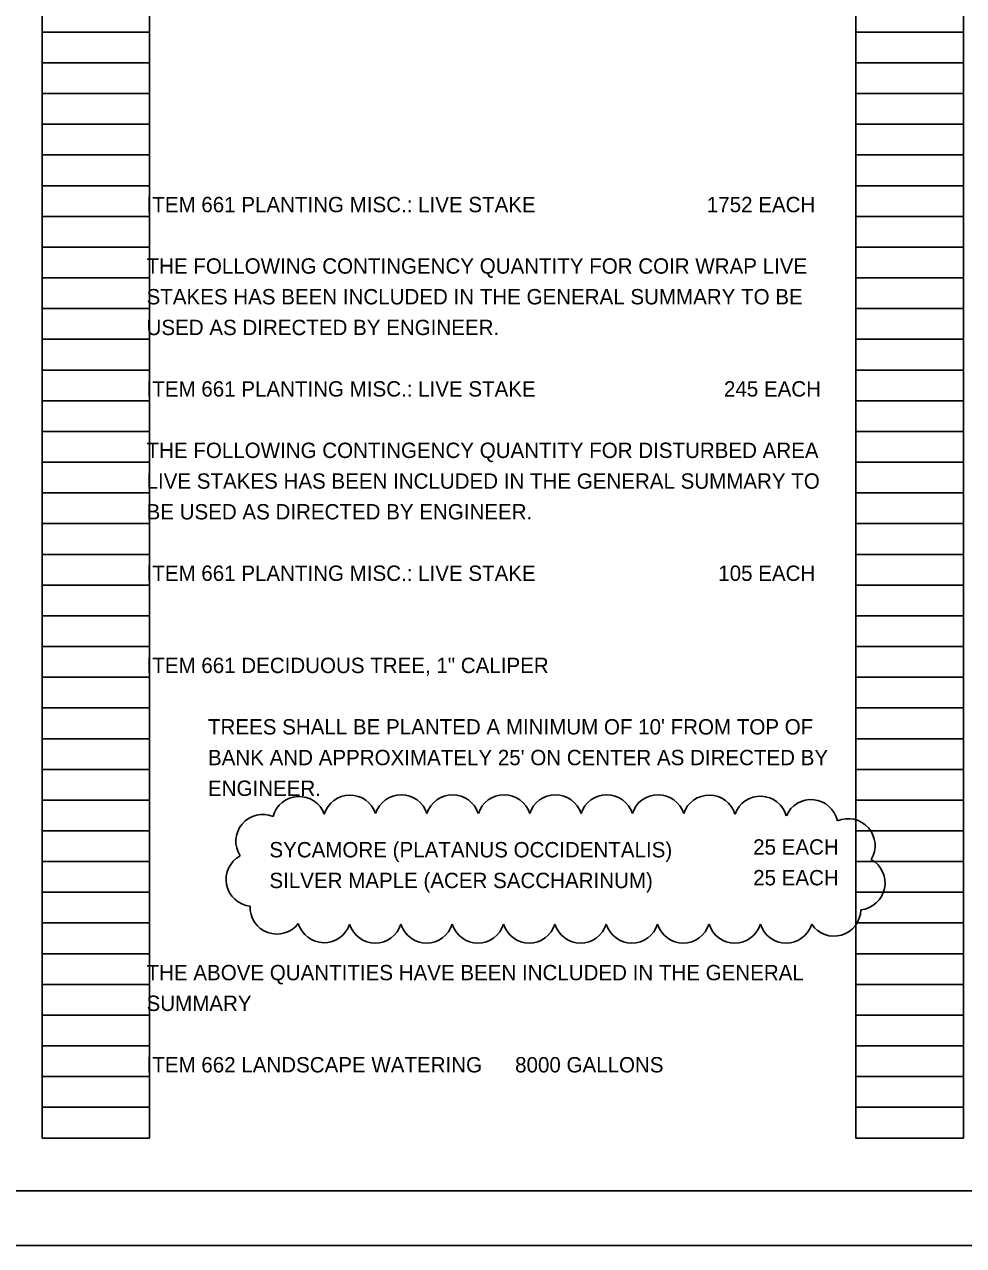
# Model space of a CAD drawing. Extents: x 0 to 34, y 0 to 22.
# Drawn here: x 16.1 to 24.66, y 0 to 11.13 of the extents above; entities that cross this region are included whole.
import ezdxf

# ---------------------------------------------------------------- set-up
doc = ezdxf.new("R2010")
doc.units = 0
for name, color, linetype in [('CS-ALGN-CNTR', 7, 'Continuous'), ('CS-ALGN-TEXT', 7, 'Continuous'), ('CS-ANNO-MATC', 7, 'Continuous'), ('CS-ANNO-MATC-MASK', 7, 'Continuous'), ('CS-ANNO-TABL', 7, 'Continuous')]:
    doc.layers.add(name, color=color, linetype=linetype)

msp = doc.modelspace()

# ---------------------------------------------------------------- linework, layer by layer
at = {"layer": 'CS-ALGN-CNTR'}
msp.add_lwpolyline([(0, 0), (34, 0), (34, 22), (0, 22)], close=True, dxfattribs=at)
at = {"layer": 'CS-ALGN-TEXT'}
msp.add_lwpolyline([(1.5, 21.5), (33.5, 21.5), (33.5, 0.5), (1.5, 0.5)], close=True, dxfattribs=at)
at = {"layer": 'CS-ANNO-MATC-MASK'}
for p, q in [((16.26, 0.98), (16.26, 21.14)), ((17.24, 0.98), (17.24, 21.14)), ((23.68, 0.98), (23.68, 21.14)), ((24.66, 0.98), (24.66, 21.14)), ((16.26, 11.06), (17.24, 11.06)), ((23.68, 11.06), (24.66, 11.06)), ((16.26, 10.78), (17.24, 10.78)), ((23.68, 10.78), (24.66, 10.78)), ((16.26, 10.5), (17.24, 10.5)), ((23.68, 10.5), (24.66, 10.5)), ((16.26, 10.22), (17.24, 10.22)), ((23.68, 10.22), (24.66, 10.22)), ((16.26, 9.94), (17.24, 9.94)), ((23.68, 9.94), (24.66, 9.94)), ((16.26, 9.66), (17.24, 9.66)), ((23.68, 9.66), (24.66, 9.66)), ((16.26, 9.38), (17.24, 9.38)), ((23.68, 9.38), (24.66, 9.38)), ((16.26, 9.1), (17.24, 9.1)), ((23.68, 9.1), (24.66, 9.1)), ((16.26, 8.82), (17.24, 8.82)), ((23.68, 8.82), (24.66, 8.82)), ((16.26, 8.54), (17.24, 8.54)), ((23.68, 8.54), (24.66, 8.54)), ((16.26, 8.26), (17.24, 8.26)), ((23.68, 8.26), (24.66, 8.26)), ((16.26, 7.98), (17.24, 7.98)), ((23.68, 7.98), (24.66, 7.98)), ((16.26, 7.7), (17.24, 7.7)), ((23.68, 7.7), (24.66, 7.7)), ((16.26, 7.42), (17.24, 7.42)), ((23.68, 7.42), (24.66, 7.42)), ((16.26, 7.14), (17.24, 7.14)), ((23.68, 7.14), (24.66, 7.14)), ((16.26, 6.86), (17.24, 6.86)), ((23.68, 6.86), (24.66, 6.86)), ((16.26, 6.58), (17.24, 6.58)), ((23.68, 6.58), (24.66, 6.58)), ((16.26, 6.3), (17.24, 6.3)), ((23.68, 6.3), (24.66, 6.3)), ((16.26, 6.02), (17.24, 6.02)), ((23.68, 6.02), (24.66, 6.02)), ((16.26, 5.74), (17.24, 5.74)), ((23.68, 5.74), (24.66, 5.74)), ((16.26, 5.46), (17.24, 5.46)), ((23.68, 5.46), (24.66, 5.46)), ((16.26, 5.18), (17.24, 5.18)), ((23.68, 5.18), (24.66, 5.18)), ((16.26, 4.9), (17.24, 4.9)), ((23.68, 4.9), (24.66, 4.9)), ((16.26, 4.62), (17.24, 4.62)), ((23.68, 4.62), (24.66, 4.62)), ((16.26, 4.34), (17.24, 4.34)), ((23.68, 4.34), (24.66, 4.34)), ((16.26, 4.06), (17.24, 4.06)), ((23.68, 4.06), (24.66, 4.06)), ((16.26, 3.78), (17.24, 3.78)), ((23.68, 3.78), (24.66, 3.78)), ((16.26, 3.5), (17.24, 3.5)), ((23.68, 3.5), (24.66, 3.5)), ((16.26, 3.22), (17.24, 3.22)), ((23.68, 3.22), (24.66, 3.22)), ((16.26, 2.94), (17.24, 2.94)), ((23.68, 2.94), (24.66, 2.94)), ((16.26, 2.66), (17.24, 2.66)), ((23.68, 2.66), (24.66, 2.66)), ((16.26, 2.38), (17.24, 2.38)), ((23.68, 2.38), (24.66, 2.38)), ((16.26, 2.1), (17.24, 2.1)), ((23.68, 2.1), (24.66, 2.1)), ((16.26, 1.82), (17.24, 1.82)), ((23.68, 1.82), (24.66, 1.82)), ((16.26, 1.54), (17.24, 1.54)), ((23.68, 1.54), (24.66, 1.54)), ((16.26, 1.26), (17.24, 1.26)), ((23.68, 1.26), (24.66, 1.26)), ((16.26, 0.98), (17.24, 0.98)), ((23.68, 0.98), (24.66, 0.98))]:
    msp.add_line(p, q, dxfattribs=at)
at = {"layer": 'CS-ANNO-TABL'}
for centre, start, end in [((18.603, 3.848), 20.1591, 165.1591), ((19.068, 3.861), 18.1234, 163.1234), ((19.535, 3.864), 17.5117, 162.5117), ((20.003, 3.864), 17.5, 162.5), ((20.472, 3.864), 17.5, 162.5), ((20.94, 3.864), 17.5, 162.5), ((21.408, 3.864), 17.5, 162.5), ((21.876, 3.864), 17.4512, 162.4512), ((22.343, 3.861), 16.8459, 161.8459), ((22.809, 3.851), 15.5867, 160.5867), ((23.271, 3.82), 11.8643, 156.8643), ((18.272, 3.684), 67.4687, 212.4687), ((23.61, 3.646), 328.7399, 113.7399), ((18.183, 3.337), 118.699, 263.699), ((23.701, 3.304), 275.8946, 60.8946), ((18.401, 3.084), 177.7193, 322.7193), ((23.48, 3.065), 213.8943, 358.8943), ((18.831, 3.005), 196.6241, 341.6241), ((19.298, 3.002), 197.5, 342.5), ((19.766, 3.002), 197.5, 342.5), ((20.234, 3.002), 197.5, 342.5), ((20.702, 3.002), 197.5, 342.5), ((21.17, 3.002), 197.5, 342.5), ((21.638, 3.002), 197.5, 342.5), ((22.106, 3.002), 197.5, 342.5), ((22.575, 3.002), 197.5, 342.5), ((23.043, 3.002), 197.5, 342.5)]:
    msp.add_arc(centre, 0.245, start, end, dxfattribs=at)

# ---------------------------------------------------------------- texts
at = {"layer": 'CS-ANNO-MATC'}
for s, p in [('ITEM 661 PLANTING MISC.: LIVE STAKE                              1752 EACH', (17.213, 9.418)), ('THE FOLLOWING CONTINGENCY QUANTITY FOR COIR WRAP LIVE ', (17.213, 8.858)), ('STAKES HAS BEEN INCLUDED IN THE GENERAL SUMMARY TO BE ', (17.213, 8.578)), ('USED AS DIRECTED BY ENGINEER.', (17.213, 8.298)), ('ITEM 661 PLANTING MISC.: LIVE STAKE                                 245 EACH', (17.213, 7.738)), ('THE FOLLOWING CONTINGENCY QUANTITY FOR DISTURBED AREA ', (17.213, 7.178)), ('LIVE STAKES HAS BEEN INCLUDED IN THE GENERAL SUMMARY TO ', (17.213, 6.898)), ('BE USED AS DIRECTED BY ENGINEER.', (17.213, 6.618)), ('ITEM 661 PLANTING MISC.: LIVE STAKE                                105 EACH', (17.213, 6.058)), ('ITEM 661 DECIDUOUS TREE, 1" CALIPER ', (17.213, 5.218)), ("TREES SHALL BE PLANTED A MINIMUM OF 10' FROM TOP OF ", (17.773, 4.658)), ("BANK AND APPROXIMATELY 25' ON CENTER AS DIRECTED BY ", (17.773, 4.378)), ('ENGINEER.', (17.773, 4.098)), ('SYCAMORE (PLATANUS OCCIDENTALIS)', (18.333, 3.538)), ('25 EACH', (22.743, 3.563)), ('SILVER MAPLE (ACER SACCHARINUM)', (18.333, 3.258)), ('25 EACH', (22.743, 3.283)), ('THE ABOVE QUANTITIES HAVE BEEN INCLUDED IN THE GENERAL ', (17.213, 2.418)), ('SUMMARY', (17.213, 2.138)), ('ITEM 662 LANDSCAPE WATERING', (17.213, 1.578)), ('8000 GALLONS', (20.573, 1.578))]:
    msp.add_text(s, height=0.14, dxfattribs=at).set_placement(p)

doc.saveas('drawing.dxf')
